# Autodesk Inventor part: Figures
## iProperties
Shininess: 65.0
Angle Display Precision: 2
Document Length Units: 11269
Document Angle Units: 11279
Document Time Units: 11290
Document Mass Units: 11283
Document Length Units Precision: 3
Document Angle Units Precision: 2
Created: 2001-11
Part Number: Figures
Document SubType Name: Modeling
Designer: Renu Muthoo
Density: 0.0
Volumn: 0.0
Area: 0.0
PropertySet Name: Model Information
Control State: 0
Master: False
Checked Out: False
Author: Renu Muthoo
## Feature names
1. Extrusion1
2. Extrusion2
3. Extrusion3
4. Hole1
